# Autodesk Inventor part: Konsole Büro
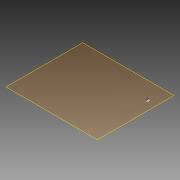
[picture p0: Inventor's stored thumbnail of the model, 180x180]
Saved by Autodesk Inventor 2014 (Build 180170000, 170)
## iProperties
Created: 2013-09
Part Number: Konsole Büro
Material: Stahl
Document SubType Name: Modeling
Designer: Stefan Tammegger
Mass: 1413 g
Surface Area: 416 cm^2
Volume: 180 cm^3
Density: 7.85 g/cm^3
Appearance: Stahl
Author: Stefan Tammegger
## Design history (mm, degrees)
workplane "Arbeitsebene1"
sketch "Skizze1"
  geometry: L1 (4517.989, 2739.717)-(4517.989, 2587.717) reference; L2 (4443.785, 2587.717)-(4443.785, 2739.717) reference; L3 (4443.785, 2739.717)-(4517.989, 2739.717) reference; L4 (4517.989, 2587.717)-(4443.785, 2587.717) reference; L5 (4430.887, 2753.717)-(4530.887, 2753.717); L6 (4530.887, 2753.717)-(4530.887, 2573.717); L7 (4530.887, 2573.717)-(4430.887, 2573.717); L8 (4430.887, 2573.717)-(4430.887, 2753.717); L9 (4480.887, 2739.717)-(4480.887, 2587.717); L10 (4443.785, 2663.717)-(4517.989, 2663.717); 1 further point
  constraints: 12 end point, 4 midpoint, 2 parallel, 1 horizontal, 1 perpendicular, 2 other
  dimensions: "d0" = 100 distance of L5.start L5.end; "d1" = 180 distance of L5.end L6.end
extrude "Extrusion1" new body sketch "Skizze1" distance "d2" = 10; taper "d3" = 0 deg
sketch "Skizze2"
  geometry: L1 (4443.785, 2739.717)-(4517.989, 2739.717) reference; L2 (4517.989, 2587.717)-(4443.785, 2587.717) reference; L3 (4443.785, 2587.717)-(4443.785, 2739.717) reference; L4 (4517.989, 2739.717)-(4517.989, 2587.717) reference; L5 (4480.887, 2739.717)-(4480.887, 2587.717); L6 (4492.989, 2612.717)-(4468.785, 2612.717); L7 (4468.785, 2612.717)-(4468.785, 2714.717); L8 (4468.785, 2714.717)-(4492.989, 2714.717); L9 (4492.989, 2714.717)-(4492.989, 2612.717); 3 further points
  constraints: 10 end point, 4 midpoint, 3 other
  dimensions: "d4" = 25 distance between parallel lines of L4 L9
hole "Bohrung1" sketch "Skizze2" at (4480.887, 2714.717), (4480.887, 2612.717) diameter "d5" = 14; stored, may be unused: countersink angle "d9" = 90 deg, drill point angle "d11" = 118 deg; dims "d6" = 6, "d7" = 4, "d8" = 2, "d10" = 8
workplane "Arbeitsebene2"
sketch "Skizze3"
  geometry: L1 (-1082.429, -4408.116)-(12.898, -15) reference; L2 (12.898, -15)-(-11.294, -112.03); L3 (22.389, -10)-(-3.532, -113.965); L4 (-11.294, -112.03)-(-3.532, -113.965); L5 (12.898, -15)-(14.145, -10); L6 (22.389, -10)-(14.145, -10); 3 further points; 1 other entity
  constraints: 10 end point, 2 perpendicular, 1 horizontal, 1 parallel, 1 point on line, 3 other
  dimensions: "d12" = 100 distance of L1.end L2.end; "d13" = 8 distance between parallel lines of L3 L1
extrude "Extrusion2" new body sketch "Skizze3" stored distance "d14" = 120; taper "d15" = 0 deg
sketch "Skizze4"
  geometry: L1 (0, 0)-(0, 120) reference; L2 (-105.153, 120)-(0, 120) reference; L3 (-100, 120)-(-100, 0) reference; L4 (0, 0)-(-105.153, 0) reference; L5 (-25, 95)-(-25, 25); L6 (-25, 25)-(-75, 25); L7 (-75, 25)-(-75, 95); L8 (-75, 95)-(-25, 95); 3 further points
  constraints: 8 end point, 2 coincident, 3 other
  dimensions: "d16" = 25 distance between parallel lines of L1 L5
hole "Bohrung2" sketch "Skizze4" at (-25, 25), (-25, 95) diameter "d18" = 10.106; stored, may be unused: countersink angle "d22" = 82 deg, drill point angle "d24" = 118 deg; dims "d19" = 6, "d20" = 3.023, "d21" = 2, "d23" = 8
node "Volumenkörper1"
node "Referenz1"
node "Referenz2"
node "Referenz3"
node "Referenz4"
node "Referenz5"
node "Referenz6"
node "Referenz7"
node "Referenz8"
node "Referenz9"
node "Volumenkörper2"
